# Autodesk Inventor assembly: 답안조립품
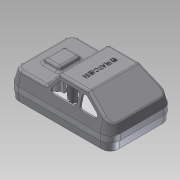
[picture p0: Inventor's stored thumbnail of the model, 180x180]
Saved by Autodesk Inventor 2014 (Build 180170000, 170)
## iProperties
Created: 2015-05
Part Number: 답안조립품
Document SubType Name: Assembly
Designer: Administrator
Author: Administrator
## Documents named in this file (4)
- C:\Documents and Settings\Administrator\바탕 화면\450508V1028\답안조립품.iam
- C:\Documents and Settings\Administrator\바탕 화면\450508V1028\본체.ipt
- C:\Documents and Settings\Administrator\바탕 화면\450508V1028\커버.ipt
- C:\Documents and Settings\Administrator\바탕 화면\450508V1028\바퀴.ipt
